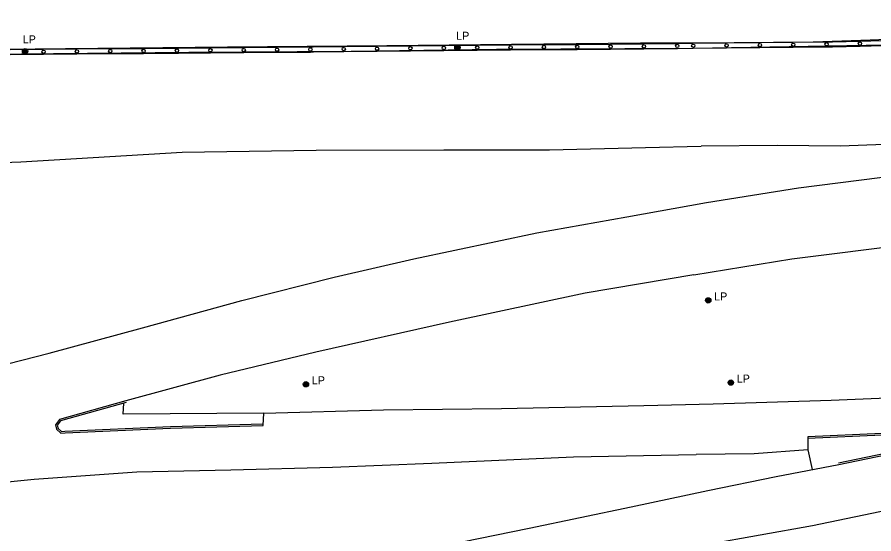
# Model space of a CAD drawing. Extents: x 2402803 to 2427059, y 6985292 to 6997652.
# Drawn here: x 2418992 to 2419506, y 6991141 to 6991451 of the extents above; entities that cross this region are included whole.
import ezdxf

# ---------------------------------------------------------------- set-up
doc = ezdxf.new("R2010")
doc.units = 0
for name, color, linetype in [('p_dtm sidewalk', 7, 'Continuous'), ('p_road - paved curb', 7, 'Continuous'), ('p_road conc barrier', 7, 'Continuous'), ('p_utility manhole', 7, 'Continuous')]:
    doc.layers.add(name, color=color, linetype=linetype)

msp = doc.modelspace()

# ---------------------------------------------------------------- linework, layer by layer
at = {"layer": 'p_dtm sidewalk'}
for points in [[(2419140.44, 6991213.82), (2419056.04, 6991213.17), (2419056.53, 6991219.91)], [(2419466.62, 6991191.78), (2419469.22, 6991180.03)]]:
    msp.add_lwpolyline(points, dxfattribs=at)
at = {"layer": 'p_road - paved curb'}
for points in [[(2419398.65, 6991436), (2419469.86, 6991436.57), (2419504, 6991437.64), (2419540.4, 6991439.06), (2419618.07, 6991438.88), (2419706.11, 6991439.68), (2419808.06, 6991441.47), (2419898.19, 6991442.94), (2419978.51, 6991443.81), (2420059.34, 6991446.46), (2420095.96, 6991451.13), (2420116.56, 6991451.34)], [(2419397.76, 6991432.64), (2419478.28, 6991434.07), (2419513.14, 6991434.72), (2419555.05, 6991433.42), (2419611.03, 6991435.55), (2419685.55, 6991436.72), (2419767.77, 6991438.2), (2419855.4, 6991439.63), (2419934.07, 6991439.79), (2420021.41, 6991441.95), (2420061.35, 6991442.86), (2420114.38, 6991442.07)], [(2418329.91, 6991425.47), (2418376.12, 6991425.9), (2418451.16, 6991426.99), (2418534.43, 6991428.3), (2418625.37, 6991428.81), (2418726.33, 6991429.78), (2418841.22, 6991431.11), (2418930.03, 6991431.56), (2419021.5, 6991432.57), (2419118.7, 6991433.44), (2419214.1, 6991434.34), (2419288.84, 6991435.15), (2419366.26, 6991435.94), (2419398.65, 6991436)], [(2418330.64, 6991422.57), (2418376.33, 6991423.52), (2418450.16, 6991424.74), (2418531.75, 6991425.31), (2418612.82, 6991425.65), (2418690.12, 6991426.44), (2418758.52, 6991427.06), (2418844.23, 6991428.03), (2418918.44, 6991428.5), (2419014.37, 6991429.56), (2419095.43, 6991430.38), (2419192.72, 6991430.98), (2419279.92, 6991432.07), (2419356.93, 6991432.49), (2419397.76, 6991432.64)], [(2418350.28, 6991354.17), (2418373.03, 6991354.75), (2418443.52, 6991355.49), (2418519.5, 6991354.97), (2418595.24, 6991355.6), (2418674.87, 6991357.09), (2418745.82, 6991357.81), (2418819.67, 6991358.36), (2418884.66, 6991360.2), (2418935.13, 6991362.3), (2418994.78, 6991364.63), (2419091.42, 6991370.32), (2419171.78, 6991371.62), (2419248.3, 6991371.71), (2419311.63, 6991371.74), (2419369.32, 6991373.1), (2419402.63, 6991373.95)], [(2419534.11, 6991375.79), (2419486.04, 6991374.05), (2419448.48, 6991374.37), (2419402.63, 6991373.95)], [(2419398.31, 6991296.78), (2419457.01, 6991306.36), (2419528.69, 6991315.3), (2419597.12, 6991323.69), (2419664.58, 6991330.72), (2419750.32, 6991338.34), (2419835.83, 6991344.31), (2419912.58, 6991349.68), (2419995.76, 6991355.22), (2420087.15, 6991361.05), (2420117.39, 6991362.44)], [(2419405.74, 6991340.13), (2419460.95, 6991348.89), (2419534.95, 6991358.44), (2419594.84, 6991365.69)], [(2418504.29, 6991114.18), (2418535.86, 6991122.7), (2418585.17, 6991135.42), (2418626.44, 6991146.26), (2418664.78, 6991157.82), (2418705.59, 6991169.48), (2418754.62, 6991181.79), (2418802.74, 6991195.09), (2418859.57, 6991209.43), (2418907.85, 6991222.69), (2418954.63, 6991235.29), (2419011.63, 6991249.9), (2419067.67, 6991265.11), (2419127.27, 6991281.51), (2419182.52, 6991295.45), (2419230.28, 6991306.37), (2419304.04, 6991321.95), (2419358, 6991331.66), (2419405.74, 6991340.13)], [(2419409.74, 6991219.46), (2419480.53, 6991221.72), (2419547.55, 6991224.36), (2419602.87, 6991228.53), (2419652.92, 6991235.63), (2419706.58, 6991242.55), (2419771.73, 6991252.89), (2419843.25, 6991266.8), (2419913.12, 6991279.82), (2419977.41, 6991292.36), (2420050.12, 6991306.92), (2420117.57, 6991316.58)], [(2419398.31, 6991296.78), (2419332.98, 6991285.78), (2419251.74, 6991268.46), (2419171.64, 6991250.39), (2419114.26, 6991236.57), (2419057.57, 6991221.24)], [(2420120.11, 6991276.87), (2420045.45, 6991263.49), (2419969.62, 6991248.62), (2419908.18, 6991237.21), (2419844.83, 6991223.71), (2419760.02, 6991206.34), (2419722.74, 6991198.57), (2419666.72, 6991186.89), (2419604.48, 6991172.74), (2419567.93, 6991164.25), (2419527.64, 6991156.06), (2419520.34, 6991156.94), (2419469.4, 6991146.32), (2419406.69, 6991135.17)], [(2419057.57, 6991221.24), (2419017.81, 6991210.13), (2419015.41, 6991206.94), (2419016.1, 6991204.19), (2419018.78, 6991201.77), (2419021.19, 6991201.99), (2419084.49, 6991204.84), (2419139.92, 6991206.45)], [(2419057.84, 6991220.28), (2419018.41, 6991209.26), (2419016.5, 6991206.72), (2419017, 6991204.73), (2419019.13, 6991202.81), (2419021.12, 6991202.99), (2419084.45, 6991205.84), (2419139.89, 6991207.45)], [(2419139.92, 6991206.48), (2419140.33, 6991213.82), (2419212.21, 6991215.8), (2419282.82, 6991216.56), (2419368.18, 6991218.48), (2419409.74, 6991219.46)], [(2419485.09, 6991183.11), (2419530.52, 6991192.46), (2419566.57, 6991199.8), (2419566.35, 6991203.81), (2419511.17, 6991201.66), (2419466.59, 6991199.71)], [(2419484.89, 6991184.09), (2419530.32, 6991193.44), (2419565.52, 6991200.61), (2419565.41, 6991202.77), (2419511.21, 6991200.66), (2419466.63, 6991198.71)], [(2419466.59, 6991199.71), (2419466.62, 6991191.78), (2419434.45, 6991189.39), (2419399.52, 6991188.99)], [(2418532.12, 6991081.51), (2418538.81, 6991083.26), (2418591.89, 6991097.7), (2418648.61, 6991112.21), (2418688.15, 6991123.2), (2418743.5, 6991135.87), (2418799.33, 6991147.8), (2418843.66, 6991154.38), (2418906.7, 6991163.7), (2418948.89, 6991168.89), (2419002.64, 6991174.26), (2419064.17, 6991178.68), (2419120.57, 6991179.92), (2419181.48, 6991181.42), (2419241.1, 6991183.81), (2419326.04, 6991187.65), (2419399.52, 6991188.99)], [(2419406.64, 6991167.41), (2419447.6, 6991175.84), (2419485.09, 6991183.11)], [(2418599.73, 6991004.38), (2418624.74, 6991009.36), (2418625.61, 6991006.43), (2418722.39, 6991026.24), (2418806, 6991043.72), (2418900.21, 6991062.86), (2418988.09, 6991081.44), (2419064.29, 6991096.65), (2419133.65, 6991111.09), (2419230.01, 6991130.78), (2419299.54, 6991144.95), (2419360.7, 6991157.62), (2419406.64, 6991167.41)]]:
    msp.add_lwpolyline(points, dxfattribs=at)
at = {"layer": 'p_road conc barrier'}
for p, q in [((2419188.3, 6991433.66), (2419208.3, 6991433.9)), ((2419208.3, 6991433.9), (2419228.3, 6991434.14)), ((2419228.3, 6991434.14), (2419248.3, 6991434.38)), ((2419268.31, 6991434.56), (2419288.31, 6991434.7)), ((2419288.31, 6991434.7), (2419308.31, 6991434.85)), ((2419308.31, 6991434.85), (2419328.31, 6991434.99)), ((2419328.31, 6991434.99), (2419348.31, 6991435.13)), ((2419368.29, 6991435.29), (2419388.29, 6991435.55)), ((2419388.29, 6991435.55), (2419397.84, 6991435.67)), ((2419397.84, 6991435.67), (2419417.84, 6991435.89)), ((2419417.84, 6991435.89), (2419437.84, 6991436.11)), ((2419437.84, 6991436.11), (2419457.84, 6991436.32)), ((2419457.84, 6991436.32), (2419477.84, 6991436.54)), ((2419497.79, 6991436.97), (2419517.79, 6991437.44)), ((2419497.86, 6991433.97), (2419517.86, 6991434.45)), ((2419008.32, 6991432.12), (2419028.32, 6991432.28)), ((2419008.35, 6991429.12), (2419028.35, 6991429.28)), ((2419028.32, 6991432.28), (2419048.32, 6991432.45)), ((2419028.35, 6991429.28), (2419048.35, 6991429.45)), ((2419048.32, 6991432.45), (2419068.32, 6991432.61)), ((2419048.35, 6991429.45), (2419068.34, 6991429.61)), ((2419068.32, 6991432.61), (2419088.32, 6991432.77)), ((2419068.34, 6991429.61), (2419088.34, 6991429.77)), ((2419108.32, 6991432.94), (2419128.32, 6991433.1)), ((2419108.34, 6991429.94), (2419128.34, 6991430.1)), ((2419128.32, 6991433.1), (2419148.32, 6991433.26)), ((2419128.34, 6991430.1), (2419148.34, 6991430.26)), ((2419148.32, 6991433.26), (2419168.32, 6991433.43)), ((2419148.34, 6991430.26), (2419168.34, 6991430.43)), ((2419188.34, 6991430.66), (2419208.34, 6991430.9)), ((2419208.34, 6991430.9), (2419228.34, 6991431.14)), ((2419228.34, 6991431.14), (2419248.33, 6991431.38)), ((2419268.33, 6991431.56), (2419288.33, 6991431.7)), ((2419288.33, 6991431.7), (2419308.33, 6991431.85)), ((2419308.33, 6991431.85), (2419328.33, 6991431.99)), ((2419328.33, 6991431.99), (2419348.33, 6991432.13)), ((2419368.33, 6991432.29), (2419388.33, 6991432.55)), ((2419388.33, 6991432.55), (2419397.88, 6991432.67)), ((2419397.88, 6991432.67), (2419417.88, 6991432.89)), ((2419417.88, 6991432.89), (2419437.87, 6991433.11)), ((2419437.87, 6991433.11), (2419457.87, 6991433.32)), ((2419457.87, 6991433.32), (2419477.87, 6991433.54))]:
    msp.add_line(p, q, dxfattribs=at)
for points in [[(2419168.32, 6991433.43), (2419170.06, 6991433.44), (2419188.3, 6991433.66)], [(2419248.3, 6991434.38), (2419255.95, 6991434.47), (2419268.31, 6991434.56)], [(2419348.31, 6991435.13), (2419365.7, 6991435.26), (2419368.29, 6991435.29)], [(2419477.84, 6991436.54), (2419481.28, 6991436.58), (2419497.79, 6991436.97)], [(2419477.87, 6991433.54), (2419481.33, 6991433.58), (2419497.86, 6991433.97)], [(2418988.32, 6991431.93), (2418999.89, 6991432.05), (2419008.32, 6991432.12)], [(2418988.35, 6991428.93), (2418999.91, 6991429.05), (2419008.35, 6991429.12)], [(2419088.32, 6991432.77), (2419089.21, 6991432.78), (2419108.32, 6991432.94)], [(2419088.34, 6991429.77), (2419089.23, 6991429.78), (2419108.34, 6991429.94)], [(2419168.34, 6991430.43), (2419170.09, 6991430.44), (2419188.34, 6991430.66)], [(2419248.33, 6991431.38), (2419255.98, 6991431.47), (2419268.33, 6991431.56)], [(2419348.33, 6991432.13), (2419365.73, 6991432.26), (2419368.33, 6991432.29)]]:
    msp.add_lwpolyline(points, dxfattribs=at)
for centre in [(2419228.32, 6991432.64), (2419248.32, 6991432.88), (2419268.32, 6991433.06), (2419288.32, 6991433.2), (2419308.32, 6991433.35), (2419328.32, 6991433.49), (2419348.32, 6991433.63), (2419368.31, 6991433.79), (2419388.31, 6991434.05), (2419397.86, 6991434.17), (2419417.86, 6991434.39), (2419437.86, 6991434.61), (2419457.86, 6991434.82), (2419477.85, 6991435.04), (2419497.83, 6991435.47), (2419008.34, 6991430.62), (2419028.34, 6991430.78), (2419048.33, 6991430.95), (2419068.33, 6991431.11), (2419088.33, 6991431.27), (2419108.33, 6991431.44), (2419128.33, 6991431.6), (2419148.33, 6991431.76), (2419168.33, 6991431.93), (2419188.32, 6991432.16), (2419208.32, 6991432.4)]:
    msp.add_circle(centre, 1, dxfattribs=at)
at = {"layer": 'p_utility manhole'}
for centre, radius in [((2419256.49, 6991433.14), 1.6), ((2419256.49, 6991433.14), 1.3), ((2419256.49, 6991433.14), 1), ((2419256.49, 6991433.14), 0.539), ((2418997.24, 6991430.85), 1.6), ((2418997.24, 6991430.85), 1.3), ((2418997.24, 6991430.85), 1), ((2418997.24, 6991430.85), 0.539), ((2418997.24, 6991430.85), 0.192), ((2419256.49, 6991433.14), 0.192), ((2419406.86, 6991281.47), 1.6), ((2419406.86, 6991281.47), 1.3), ((2419406.86, 6991281.47), 1), ((2419406.86, 6991281.47), 0.539), ((2419406.86, 6991281.47), 0.192), ((2419420.4, 6991232.17), 1.6), ((2419420.4, 6991232.17), 1.3), ((2419165.64, 6991231.17), 1.6), ((2419165.64, 6991231.17), 1.3), ((2419165.64, 6991231.17), 1), ((2419165.64, 6991231.17), 0.539), ((2419165.64, 6991231.17), 0.192), ((2419420.4, 6991232.17), 1), ((2419420.4, 6991232.17), 0.539), ((2419420.4, 6991232.17), 0.192)]:
    msp.add_circle(centre, radius, dxfattribs=at)

# ---------------------------------------------------------------- texts
for p in [(2418992.28, 6991435.63), (2419252.19, 6991437.76), (2419406.86, 6991281.47), (2419165.64, 6991231.17), (2419420.4, 6991232.17)]:
    msp.add_text('  LP', height=4.8, dxfattribs=at).set_placement(p)

doc.saveas('drawing.dxf')
